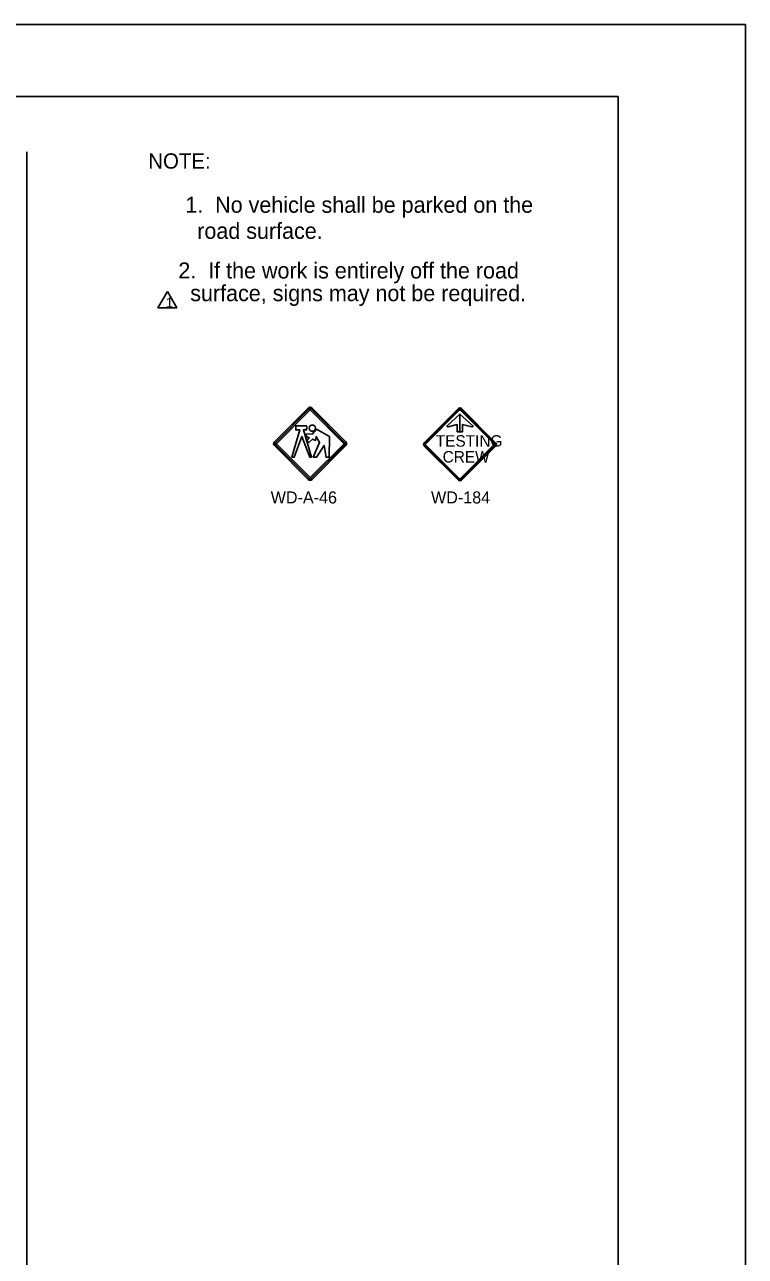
# Model space of a CAD drawing. Extents: x 1351 to 1567, y 178 to 457.
# Drawn here: x 1459 to 1567.4, y 271.7 to 456.9 of the extents above; entities that cross this region are included whole.
import ezdxf

# ---------------------------------------------------------------- set-up
doc = ezdxf.new("R2010")
doc.units = 0
for name, color, linetype in [('Level 1', 7, 'Continuous'), ('Level 10', 7, 'Continuous'), ('Level 2', 7, 'Continuous'), ('Level 3', 7, 'Continuous'), ('Level 44', 7, 'Continuous'), ('Level 60', 7, 'Continuous'), ('Level 61', 7, 'Continuous'), ('Level 62', 7, 'Continuous')]:
    doc.layers.add(name, color=color, linetype=linetype)

# ---------------------------------------------------------------- blocks, each defined once
blk = doc.blocks.new('REV1')
at = {"layer": 'Level 1'}
blk.add_lwpolyline([(0.114, 1.689), (-1.305, -0.781), (1.533, -0.781)], close=True, dxfattribs=at)
blk.add_text('1', height=1.448, rotation=360, dxfattribs=at).set_placement((-0.113, -0.724))

msp = doc.modelspace()

# ---------------------------------------------------------------- linework, layer by layer
at = {"layer": 'Level 1'}
for p, q in [((1496.57, 394.19), (1501.65, 399.27)), ((1496.71, 394.05), (1501.79, 399.13)), ((1496.85, 393.91), (1501.93, 398.99)), ((1501.9, 399.53), (1501.9, 399.53)), ((1501.93, 399.56), (1501.93, 399.56)), ((1501.94, 398.99), (1507.03, 393.91)), ((1502.08, 399.13), (1507.17, 394.05)), ((1502.22, 399.27), (1507.31, 394.19)), ((1519.09, 394.04), (1524.23, 399.18)), ((1524.32, 399.08), (1519.19, 393.95)), ((1519.19, 393.95), (1524.32, 399.08)), ((1519.28, 393.85), (1524.42, 398.99)), ((1524.47, 398.35), (1524.47, 395.71)), ((1524.52, 398.99), (1529.66, 393.85)), ((1524.71, 399.18), (1529.84, 394.04)), ((1501.65, 388.53), (1496.57, 393.62)), ((1501.79, 388.67), (1496.71, 393.76)), ((1501.93, 388.81), (1496.85, 393.9)), ((1501.9, 393.81), (1501.9, 393.81)), ((1507.03, 393.9), (1501.94, 388.81)), ((1507.17, 393.76), (1502.08, 388.67)), ((1507.31, 393.62), (1502.22, 388.53)), ((1524.23, 388.43), (1519.09, 393.56)), ((1524.42, 388.61), (1519.28, 393.75)), ((1524.49, 388.64), (1529.63, 393.78)), ((1524.49, 388.64), (1529.63, 393.78)), ((1524.49, 388.64), (1529.63, 393.78)), ((1529.63, 393.78), (1524.49, 388.64)), ((1529.66, 393.75), (1524.52, 388.61)), ((1529.84, 393.56), (1524.71, 388.43)), ((1530.08, 393.8), (1530.08, 393.8))]:
    msp.add_line(p, q, dxfattribs=at)
for points in [[(1500.38, 395.97), (1499.76, 395.97), (1499.76, 396.57), (1501.39, 396.57), (1501.39, 396.48), (1501.46, 396.48), (1501.46, 396.24), (1501.39, 396.24), (1501.39, 395.97), (1500.93, 395.97), (1502.13, 391.87), (1501.88, 391.87), (1500.7, 394.97), (1499.52, 391.87), (1499.2, 391.87)], [(1500.38, 395.97), (1499.76, 395.97), (1499.76, 396.57), (1501.39, 396.57), (1501.39, 396.48), (1501.46, 396.48), (1501.46, 396.24), (1501.39, 396.24), (1501.39, 395.97), (1500.93, 395.97), (1502.13, 391.87), (1501.88, 391.87), (1500.7, 394.97), (1499.52, 391.87), (1499.2, 391.87)], [(1501.37, 395.4), (1502.23, 395.32), (1502.91, 396.1), (1504.85, 394.98), (1504.78, 391.87), (1504.32, 391.87), (1504.04, 393.65), (1502.91, 391.87), (1502.4, 391.87), (1503.36, 394.08), (1502.85, 394.97), (1502.75, 394.41), (1502.3, 394.59), (1501.76, 394.07), (1501.43, 394.38), (1501.79, 394.81), (1501.3, 395.04)], [(1501.37, 395.4), (1502.23, 395.32), (1502.91, 396.1), (1504.85, 394.98), (1504.78, 391.87), (1504.32, 391.87), (1504.04, 393.65), (1502.91, 391.87), (1502.4, 391.87), (1503.36, 394.08), (1502.85, 394.97), (1502.75, 394.41), (1502.3, 394.59), (1501.76, 394.07), (1501.43, 394.38), (1501.79, 394.81), (1501.3, 395.04)]]:
    msp.add_lwpolyline(points, close=True, dxfattribs=at)
for centre, radius, start, end in [((1501.93, 398.98), 0.406, 45.0349, 135), ((1501.93, 398.98), 0.206, 45.0349, 135), ((1501.93, 398.98), 0.00619, 45.0349, 135), ((1524.47, 398.94), 0.336, 44.9995, 135.0002), ((1524.47, 398.94), 0.204, 44.9995, 135.0002), ((1524.47, 398.94), 0.204, 44.9995, 135.0002), ((1524.47, 398.94), 0.0714, 44.9995, 135.0002), ((1524.47, 398.94), 0.0273, 45, 135), ((1524.47, 398.94), 0.0273, 45, 135), ((1524.47, 398.94), 0.0273, 45, 135), ((1496.85, 393.9), 0.406, 135, 224.9651), ((1496.85, 393.9), 0.206, 135, 224.9651), ((1496.85, 393.9), 0.00619, 135, 224.9651), ((1507.02, 393.9), 0.00619, 315, 45.0346), ((1507.02, 393.9), 0.206, 315, 45.0346), ((1507.02, 393.9), 0.406, 315, 45.0346), ((1519.33, 393.8), 0.336, 135.0005, 225), ((1519.33, 393.8), 0.204, 135.0005, 225), ((1519.33, 393.8), 0.204, 135.0005, 225), ((1519.33, 393.8), 0.204, 135.0005, 225), ((1519.33, 393.8), 0.0714, 135.0005, 225), ((1529.61, 393.8), 0.0273, 315, 45), ((1529.61, 393.8), 0.0273, 315, 45), ((1529.61, 393.8), 0.0273, 315, 45), ((1529.61, 393.8), 0.0714, 315.0005, 44.9999), ((1529.61, 393.8), 0.204, 315.0005, 44.9999), ((1529.61, 393.8), 0.204, 315.0005, 44.9999), ((1529.61, 393.8), 0.336, 315.0005, 44.9999), ((1501.93, 388.82), 0.406, 224.965, 315), ((1501.93, 388.82), 0.206, 224.965, 315), ((1501.93, 388.82), 0.00619, 224.965, 315), ((1524.47, 388.66), 0.336, 224.9995, 315), ((1524.47, 388.66), 0.0714, 224.9995, 315), ((1524.47, 388.66), 0.0273, 225, 315), ((1524.47, 388.66), 0.0273, 225, 315), ((1524.47, 388.66), 0.0273, 225, 315)]:
    msp.add_arc(centre, radius, start, end, dxfattribs=at)
at = {"layer": 'Level 10'}
msp.add_line((1459.33, 437.79), (1459.33, 193.22), dxfattribs=at)
at = {"layer": 'Level 2'}
for centre, radius, start, end in [((1524.47, 398.94), 0.336, 44.9995, 135.0002), ((1524.47, 398.94), 0.204, 44.9995, 135.0002), ((1519.33, 393.8), 0.336, 135.0005, 225), ((1529.61, 393.8), 0.204, 315.0005, 44.9999), ((1529.61, 393.8), 0.336, 315.0005, 44.9999), ((1524.47, 388.66), 0.204, 224.9995, 315)]:
    msp.add_arc(centre, radius, start, end, dxfattribs=at)
at = {"layer": 'Level 3'}
for centre, start, end in [((1524.47, 398.94), 45, 135), ((1524.47, 398.94), 45, 135), ((1529.61, 393.8), 315, 45), ((1529.61, 393.8), 315, 45), ((1524.47, 388.66), 225, 315), ((1524.47, 388.66), 225, 315)]:
    msp.add_arc(centre, 0.0273, start, end, dxfattribs=at)
at = {"layer": 'Level 44'}
msp.add_circle((1502.26, 396.24), 0.467, dxfattribs=at)
msp.add_circle((1502.26, 396.24), 0.467, dxfattribs=at)
at = {"layer": 'Level 60'}
for p, q in [((1567.41, 456.92), (1567.41, 456.92)), ((1522.68, 396.43), (1522.68, 396.43))]:
    msp.add_line(p, q, dxfattribs=at)
for points in [[(1567.41, 456.92), (1351.41, 456.92), (1351.41, 177.92), (1567.41, 177.92)], [(1548.28, 446.11), (1361.41, 446.11), (1361.41, 188.73), (1548.28, 188.73)]]:
    msp.add_lwpolyline(points, close=True, dxfattribs=at)
for points in [[(1522.58, 396.63), (1524.47, 398.35), (1526.36, 396.63)], [(1526.25, 396.43), (1524.86, 396.79), (1524.86, 395.71), (1524.07, 395.71), (1524.07, 396.79), (1522.68, 396.43)]]:
    msp.add_lwpolyline(points, dxfattribs=at)
for centre, start, end in [((1522.66, 396.54), 132.3048, 284.4075), ((1526.28, 396.54), 255.5925, 47.6952)]:
    msp.add_arc(centre, 0.119, start, end, dxfattribs=at)
at = {"layer": 'Level 61'}
msp.add_line((1522.68, 396.43), (1522.68, 396.43), dxfattribs=at)
for points in [[(1522.58, 396.63), (1524.47, 398.35), (1526.36, 396.63)], [(1526.25, 396.43), (1524.86, 396.79), (1524.86, 395.71), (1524.07, 395.71), (1524.07, 396.79), (1522.68, 396.43)]]:
    msp.add_lwpolyline(points, dxfattribs=at)
for centre, start, end in [((1522.66, 396.54), 132.3048, 284.4075), ((1526.28, 396.54), 255.5925, 47.6952)]:
    msp.add_arc(centre, 0.119, start, end, dxfattribs=at)
at = {"layer": 'Level 62'}
for p, q in [((1519.19, 393.95), (1524.32, 399.08)), ((1524.61, 399.08), (1529.75, 393.95)), ((1522.68, 396.43), (1522.68, 396.43)), ((1524.32, 388.52), (1519.19, 393.66)), ((1529.75, 393.66), (1524.61, 388.52))]:
    msp.add_line(p, q, dxfattribs=at)
for points in [[(1522.58, 396.63), (1524.47, 398.35), (1526.36, 396.63)], [(1526.25, 396.43), (1524.86, 396.79), (1524.86, 395.71), (1524.07, 395.71), (1524.07, 396.79), (1522.68, 396.43)]]:
    msp.add_lwpolyline(points, dxfattribs=at)
for centre, radius, start, end in [((1524.47, 398.94), 0.204, 44.9995, 135.0002), ((1522.66, 396.54), 0.119, 132.3048, 284.4075), ((1526.28, 396.54), 0.119, 255.5925, 47.6952), ((1519.33, 393.8), 0.204, 135.0005, 225), ((1529.61, 393.8), 0.204, 315.0005, 44.9999), ((1524.47, 388.66), 0.204, 224.9995, 315)]:
    msp.add_arc(centre, radius, start, end, dxfattribs=at)

# ---------------------------------------------------------------- block references
at = {"layer": 'Level 1'}
msp.add_blockref('REV1', (1480.34, 415.13), dxfattribs=at)

# ---------------------------------------------------------------- texts
at = {"layer": 'Level 10'}
for s, height, p in [('NOTE:', 2.298, (1477.58, 435.27)), ('1.  No vehicle shall be parked on the ', 2.419, (1483.15, 428.63)), ('  road surface.', 2.419, (1483.15, 424.71)), ('WD-A-46', 1.813, (1496, 384.92)), ('WD-184', 1.813, (1520.12, 384.92))]:
    msp.add_text(s, height=height, dxfattribs=at).set_placement(p)
at = {"layer": 'Level 60'}
for s, p in [('2.  If the work is entirely off the road ', (1482.1, 418.75)), ('  surface, signs may not be required.', (1482.1, 415.34))]:
    msp.add_text(s, height=2.419, dxfattribs=at).set_placement(p)
at = {"layer": 'Level 62'}
for s, p in [('TESTING', (1520.84, 393.46)), ('CREW', (1521.87, 391.08))]:
    msp.add_text(s, height=1.728, rotation=360, dxfattribs=at).set_placement(p)

doc.saveas('drawing.dxf')
